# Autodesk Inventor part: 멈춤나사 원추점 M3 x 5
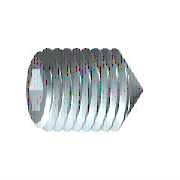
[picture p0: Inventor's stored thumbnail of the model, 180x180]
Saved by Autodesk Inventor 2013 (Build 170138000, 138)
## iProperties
IsCustomPart: 1
Created: 2012-02
Part Number: 멈춤나사 원추점 M3 x 5
Material: 강철, 연강
Description: 6각 소켓 머리 없는 멈춤 나사
Document SubType Name: Modeling
Standard: KS B 1028
Designer: mduedu
Standards Organization: KS
Language: ko-KR
Size Designation: 원추점 M3x5
Categories: <MemberInstance><Categories><Category DisplayName="조임쇠" InternalName="e4da775c-781d-43d5-af7c-5136215cf5a6" Mnemonic="FSTN"><Category DisplayName="볼트" InternalN
Density: 1 g/cm^3
Author: mduedu
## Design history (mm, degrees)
sketch "스케치1"
  geometry: L1 (0, 0)-(2.5, 0); L2 (5, 0.866)-(5, 1.5); L3 (5, 1.5)-(0, 1.5); L4 (5, 0.866)-(3, 0.866); L5 (3, 0.866)-(2.5, 0); L6 (0, -0.3)-(0, 1.8) reference; L7 (0, 1.5)-(0, 0)
  constraints: 13 end point, 3 parallel, 1 collinear, 1 perpendicular, 1 point on line
  dimensions: "d0" = 2 distance of L2.start L4.end (= INTI); "d1" = 60 deg angle of L5 L1; "d2" = 3 diameter of L3 L1 (= NND); "d3" = 1.73205 diameter of L4 L1 (= 1.1547 x SW); "d5" = 5 distance from line of L2 L3.end (= NLG)
revolve "본체" sketch "스케치1" stored, may be unused: angle "d6" = 90 deg
sketch "스케치2"
  geometry: L1 (-0.433, 0.75)-(0.433, 0.75); L2 (0.433, 0.75)-(0.866, 0); L3 (0.866, 0)-(0.433, -0.75); L4 (0.433, -0.75)-(-0.433, -0.75); L5 (-0.433, -0.75)-(-0.866, 0); L6 (-0.866, 0)-(-0.433, 0.75); 3 further points
  constraints: 12 end point, 1 coincident, 1 horizontal, 13 other
extrude "슬롯" join sketch "스케치2" taper "d7" = 0 deg; stored distance "d21" = 10
workaxis "Work Axis1"
workplane "Work Plane1"
sketch "스케치4"
  geometry: L1 (-5, 1.193)-(-4.693, 1.5) reference; L2 (-4.693, 1.5)-(-1.35, 1.5) reference; L3 (-1.35, 1.5)-(0, 0.15) reference; L4 (0, 0.15)-(0, -0.15) reference; L5 (0, -0.15)-(-1.35, -1.5) reference; L6 (-1.35, -1.5)-(-4.693, -1.5) reference; L7 (-4.693, -1.5)-(-5, -1.193) reference; L8 (-5, -1.193)-(-5, -0.75) reference; L9 (-5, -0.75)-(-2.933, -0.75) reference; L10 (-2.933, -0.75)-(-2.5, 0) reference; L11 (-2.5, 0)-(-2.933, 0.75) reference; L12 (-2.933, 0.75)-(-5, 0.75) reference; L13 (-5, 0.75)-(-5, 1.193) reference; L14 (0, 0.15)-(0.15, 0); L15 (0, -0.15)-(0.15, 0); 1 further point
  constraints: 4 end point, 1 parallel, 1 perpendicular
  node "절단 모서리 투영1"
node "작업점1"
body "Solid1"
feature "스레드" dims "d12" = 5 (= NLG), "d13" = 0
chamfer "모따기1" distance "d8" = 1.35 (computed from NND, SPD, FAWI); stored, may be unused: angle "d9" = 45 deg (= FAWI), second distance "d34" = 1.35 (computed from NND, SPD, FAWI)
chamfer "모따기2" distance "d10" = 0.30673 (= -0.5 x GD1 + 0.5 x NND); stored, may be unused: angle "d11" = 45 deg (= FAWI), second distance "d35" = 0.30673 (= -0.5 x GD1 + 0.5 x NND)
other parameters: "NND" = 3 [user parameter; used in 5 equation terms], "NLG" = 5 [user parameter; used in 2 equation terms], "INTI" = 2 [user parameter; used in 1 equation term], "FAWI" = 45 deg [user parameter; used in 4 equation terms], "SW" = 1.5 [user parameter; used in 2 equation terms], "GD1" = 2.38655 (= THREADDIA - 1.2269 x PTC) [user parameter; used in 2 equation terms], "d4" = 0, "FAWI1" = 45 deg [user parameter], "SPD" = 0.3 [user parameter; used in 2 equation terms], "d36" = 0, "d37" = 0, "GUL" = 0.30673 (= 0.61345 x PTC) [user parameter], "TOA" = 30 deg [user parameter], "THREADDIA" = 3 [user parameter; used in 1 equation term], "PTC" = 0.5 [user parameter; used in 4 equation terms], "GAL" = 0.30673 (= 0.61345 x PTC) [user parameter], "E0" = 1.7325 (= 1.155 x SW) [user parameter]
